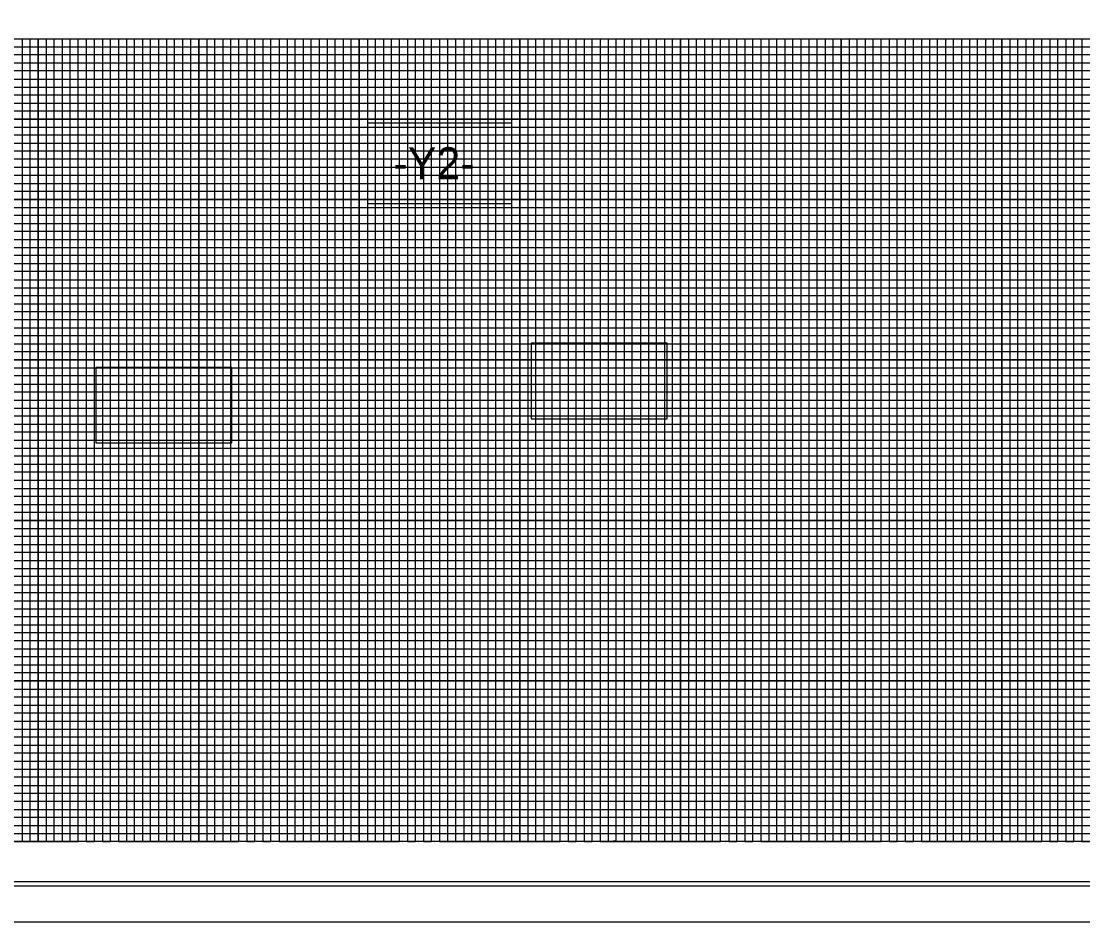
# Model space of a CAD drawing. Extents: x 1650661 to 1652901, y 832691 to 833791.
# Drawn here: x 1651694 to 1652355, y 832691 to 833252 of the extents above; entities that cross this region are included whole.
import ezdxf

# ---------------------------------------------------------------- set-up
doc = ezdxf.new("R2010")
doc.units = 0
for name, color, linetype in [('Exist Vertical Profile Horizontal Axis Label Major', 7, 'Continuous'), ('Prop Grid Mask', 7, 'Continuous'), ('Sheet Cutting Line CELL', 7, 'Continuous'), ('Sheet DOT Grid CELL', 7, 'Continuous'), ('Sheet Layout Profile Border Port 2', 7, 'Continuous'), ('Sheet Plot Border Inside CELL', 7, 'Continuous'), ('Sheet Plot Border Outside CELL', 7, 'Continuous'), ('Sheet Profile CELL', 7, 'Continuous'), ('Sheet Profile Grid Major CELL', 7, 'Continuous'), ('Sheet Profile Grid Middle CELL', 7, 'Continuous'), ('Sheet Profile Grid Minor CELL', 7, 'Continuous')]:
    doc.layers.add(name, color=color, linetype=linetype)

msp = doc.modelspace()

# ---------------------------------------------------------------- linework, layer by layer
at = {"layer": 'Prop Grid Mask'}
for points in [[(1651909.28, 833188.52), (1651909.28, 833138.52), (1651999.28, 833138.52), (1651999.28, 833188.52)], [(1652011.29, 833051.42), (1652011.29, 833004.42), (1652096.04, 833004.42), (1652096.04, 833051.42)], [(1651740.2, 833036.34), (1651740.2, 832989.34), (1651824.95, 832989.34), (1651824.95, 833036.34)]]:
    msp.add_lwpolyline(points, close=True, dxfattribs=at)
at = {"layer": 'Sheet Cutting Line CELL'}
msp.add_line((1651037.28, 832691.02), (1652721.28, 832691.02), dxfattribs=at)
at = {"layer": 'Sheet DOT Grid CELL'}
for p, q in [((1651204.28, 833241.02), (1652704.17, 833241.02)), ((1651704.28, 833241.02), (1651704.28, 832741.02)), ((1651754.28, 833241.02), (1651754.28, 832741.02)), ((1651804.28, 833241.02), (1651804.28, 832741.02)), ((1651854.28, 833241.02), (1651854.28, 832741.02)), ((1651904.28, 833241.02), (1651904.28, 832741.02)), ((1651954.28, 833241.02), (1651954.28, 832741.02)), ((1652004.28, 833241.02), (1652004.28, 832741.02)), ((1652054.28, 833241.02), (1652054.28, 832741.02)), ((1652104.28, 833241.02), (1652104.28, 832741.02)), ((1652154.28, 833241.02), (1652154.28, 832741.02)), ((1652204.28, 833241.02), (1652204.28, 832741.02)), ((1652254.28, 833241.02), (1652254.28, 832741.02)), ((1652304.28, 833241.02), (1652304.28, 832741.02)), ((1652354.28, 833241.02), (1652354.28, 832741.02)), ((1651204.28, 833191.02), (1652704.17, 833191.02)), ((1651204.28, 833141.02), (1652704.17, 833141.02)), ((1651204.28, 833091.02), (1652704.17, 833091.02)), ((1651204.28, 833041.02), (1652704.17, 833041.02)), ((1651204.28, 832991.02), (1652704.17, 832991.02)), ((1651204.28, 832941.02), (1652704.17, 832941.02)), ((1651204.28, 832891.02), (1652704.17, 832891.02)), ((1651204.28, 832841.02), (1652704.17, 832841.02)), ((1651204.28, 832791.02), (1652704.17, 832791.02))]:
    msp.add_line(p, q, dxfattribs=at)
at = {"layer": 'Sheet Layout Profile Border Port 2'}
msp.add_lwpolyline([(1651254.28, 833241.02), (1652654.28, 833241.02), (1652654.28, 832741.02), (1651254.28, 832741.02)], close=True, dxfattribs=at)
at = {"layer": 'Sheet Plot Border Inside CELL'}
msp.add_lwpolyline([(1651050.28, 832713.47), (1652716.78, 832713.47), (1652716.78, 833768.57), (1651050.28, 833768.57)], close=True, dxfattribs=at)
at = {"layer": 'Sheet Plot Border Outside CELL'}
msp.add_lwpolyline([(1651037.28, 832691.02), (1652721.28, 832691.02), (1652721.28, 833791.02), (1651037.28, 833791.02)], close=True, dxfattribs=at)
at = {"layer": 'Sheet Profile CELL'}
for p, q in [((1651204.28, 833241.02), (1652704.28, 833241.02)), ((1652704.28, 832741.02), (1651204.28, 832741.02)), ((1651204.28, 832716.02), (1652704.28, 832716.02))]:
    msp.add_line(p, q, dxfattribs=at)
msp.add_lwpolyline([(1652704.28, 833766.02), (1651204.28, 833766.02), (1651204.28, 832716.02), (1652704.28, 832716.02)], close=True, dxfattribs=at)
at = {"layer": 'Sheet Profile Grid Major CELL'}
for p, q in [((1651704.28, 833241.02), (1651754.28, 833241.02)), ((1651804.28, 833241.02), (1651854.28, 833241.02)), ((1651904.28, 833241.02), (1651954.28, 833241.02)), ((1652004.28, 833241.02), (1652054.28, 833241.02)), ((1652104.28, 833241.02), (1652154.28, 833241.02)), ((1652204.28, 833241.02), (1652254.28, 833241.02)), ((1652304.28, 833241.02), (1652354.28, 833241.02))]:
    msp.add_line(p, q, dxfattribs=at)
for points in [[(1651654.28, 832741.02), (1651704.28, 832741.02), (1651704.28, 833241.02), (1651754.28, 833241.02), (1651754.28, 832741.02), (1651804.28, 832741.02), (1651804.28, 833241.02), (1651854.28, 833241.02), (1651854.28, 832741.02), (1651904.28, 832741.02), (1651904.28, 833241.02), (1651954.28, 833241.02), (1651954.28, 832741.02), (1652004.28, 832741.02), (1652004.28, 833241.02), (1652054.28, 833241.02), (1652054.28, 832741.02), (1652104.28, 832741.02), (1652104.28, 833241.02), (1652154.28, 833241.02), (1652154.28, 832741.02), (1652204.28, 832741.02), (1652204.28, 833241.02), (1652254.28, 833241.02), (1652254.28, 832741.02), (1652304.28, 832741.02), (1652304.28, 833241.02), (1652354.28, 833241.02), (1652354.28, 832741.02), (1652404.28, 832741.02)], [(1652704.28, 833191.02), (1651204.28, 833191.02)], [(1652704.28, 833141.02), (1651204.28, 833141.02), (1651204.28, 833091.02), (1652704.28, 833091.02)], [(1652704.28, 833041.02), (1651204.28, 833041.02), (1651204.28, 832991.02), (1652704.28, 832991.02)], [(1652704.28, 832941.02), (1651204.28, 832941.02), (1651204.28, 832891.02), (1652704.28, 832891.02)], [(1652704.28, 832841.02), (1651204.28, 832841.02), (1651204.28, 832841.02), (1651204.28, 832791.02), (1652704.28, 832791.02)], [(1652704.28, 832741.02), (1651204.28, 832741.02)]]:
    msp.add_lwpolyline(points, dxfattribs=at)
at = {"layer": 'Sheet Profile Grid Middle CELL'}
for points in [[(1651679.28, 832741.02), (1651729.28, 832741.02), (1651729.28, 833241.02), (1651779.28, 833241.02), (1651779.28, 832741.02), (1651829.28, 832741.02), (1651829.28, 832741.02), (1651829.28, 833241.02), (1651879.28, 833241.02), (1651879.28, 832741.02), (1651929.28, 832741.02), (1651929.28, 833241.02), (1651979.28, 833241.02), (1651979.28, 832741.02), (1652029.28, 832741.02), (1652029.28, 833241.02), (1652079.28, 833241.02), (1652079.28, 832741.02), (1652129.28, 832741.02), (1652129.28, 833241.02), (1652179.28, 833241.02), (1652179.28, 832741.02), (1652229.28, 832741.02), (1652229.28, 833241.02), (1652279.28, 833241.02), (1652279.28, 832741.02), (1652329.28, 832741.02), (1652329.28, 833241.02), (1652379.28, 833241.02)], [(1651204.28, 833216.02), (1652704.28, 833216.02)], [(1652704.28, 833166.02), (1651204.28, 833166.02), (1651204.28, 833116.02), (1652704.28, 833116.02)], [(1652704.28, 833066.02), (1651204.28, 833066.02), (1651204.28, 833016.02), (1652704.28, 833016.02)], [(1652704.28, 832966.02), (1651204.28, 832966.02), (1651204.28, 832916.02), (1652704.28, 832916.02)], [(1652704.28, 832866.02), (1651204.28, 832866.02), (1651204.28, 832816.02), (1652704.28, 832816.02)], [(1652704.28, 832766.02), (1651204.28, 832766.02)]]:
    msp.add_lwpolyline(points, dxfattribs=at)
at = {"layer": 'Sheet Profile Grid Minor CELL'}
for p, q in [((1651254.28, 833236.02), (1652654.28, 833236.02)), ((1652654.28, 833231.02), (1651254.28, 833231.02)), ((1651254.28, 833226.02), (1652654.28, 833226.02)), ((1652654.28, 833221.02), (1651254.28, 833221.02)), ((1651254.28, 833211.02), (1652654.28, 833211.02)), ((1652654.28, 833206.02), (1651254.28, 833206.02)), ((1651254.28, 833201.02), (1652654.28, 833201.02)), ((1652654.28, 833196.02), (1651254.28, 833196.02)), ((1651254.28, 833186.02), (1652654.28, 833186.02)), ((1652654.28, 833181.02), (1651254.28, 833181.02)), ((1651254.28, 833176.02), (1652654.28, 833176.02)), ((1652654.28, 833171.02), (1651254.28, 833171.02)), ((1651254.28, 833161.02), (1652654.28, 833161.02)), ((1652654.28, 833156.02), (1651254.28, 833156.02)), ((1651254.28, 833151.02), (1652654.28, 833151.02)), ((1652654.28, 833146.02), (1651254.28, 833146.02)), ((1651254.28, 833136.02), (1652654.28, 833136.02)), ((1652654.28, 833131.02), (1651254.28, 833131.02)), ((1651254.28, 833126.02), (1652654.28, 833126.02)), ((1652654.28, 833121.02), (1651254.28, 833121.02)), ((1651254.28, 833111.02), (1652654.28, 833111.02)), ((1652654.28, 833106.02), (1651254.28, 833106.02)), ((1651254.28, 833101.02), (1652654.28, 833101.02)), ((1652654.28, 833096.02), (1651254.28, 833096.02)), ((1651254.28, 833086.02), (1652654.28, 833086.02)), ((1652654.28, 833081.02), (1651254.28, 833081.02)), ((1651254.28, 833076.02), (1652654.28, 833076.02)), ((1652654.28, 833071.02), (1651254.28, 833071.02)), ((1651254.28, 833061.02), (1652654.28, 833061.02)), ((1652654.28, 833056.02), (1651254.28, 833056.02)), ((1651254.28, 833051.02), (1652654.28, 833051.02)), ((1652654.28, 833046.02), (1651254.28, 833046.17)), ((1651254.28, 833036.02), (1652654.28, 833036.02)), ((1652654.28, 833031.02), (1651254.28, 833031.02)), ((1651254.28, 833026.02), (1652654.28, 833026.02)), ((1652654.28, 833021.02), (1651254.28, 833021.02)), ((1651254.28, 833011.02), (1652654.28, 833011.02)), ((1652654.28, 833006.02), (1651254.28, 833006.02)), ((1651254.28, 833001.02), (1652654.28, 833001.02)), ((1652654.28, 832996.02), (1651254.28, 832996.02)), ((1651254.28, 832986.02), (1652654.28, 832986.02)), ((1652654.28, 832981.02), (1651254.28, 832981.02)), ((1651254.28, 832976.02), (1652654.28, 832976.02)), ((1652654.28, 832971.02), (1651254.28, 832971.02)), ((1651254.28, 832961.02), (1652654.28, 832961.02)), ((1652654.28, 832956.02), (1651254.28, 832956.02)), ((1651254.28, 832951.02), (1652654.28, 832951.02)), ((1652654.28, 832946.02), (1651254.28, 832946.02)), ((1651254.28, 832936.02), (1652654.28, 832936.02)), ((1652654.28, 832931.02), (1651254.28, 832931.02)), ((1651254.28, 832926.02), (1652654.28, 832926.02)), ((1652654.28, 832921.02), (1651254.28, 832921.02)), ((1651254.28, 832911.02), (1652654.28, 832911.02)), ((1652654.28, 832906.02), (1651254.28, 832906.02)), ((1651254.28, 832901.02), (1652654.28, 832901.02)), ((1652654.28, 832896.02), (1651254.28, 832896.02)), ((1651254.28, 832886.02), (1652654.28, 832886.02)), ((1652654.28, 832881.02), (1651254.28, 832881.02)), ((1651254.28, 832876.02), (1652654.28, 832876.02)), ((1652654.28, 832871.02), (1651254.28, 832871.02)), ((1651254.28, 832861.02), (1652654.28, 832861.02)), ((1652654.28, 832856.02), (1651254.28, 832856.02)), ((1651254.28, 832851.02), (1652654.28, 832851.02)), ((1652654.28, 832846.02), (1651254.28, 832846.02)), ((1651254.28, 832836.02), (1652654.28, 832836.02)), ((1652654.28, 832831.02), (1651254.28, 832831.02)), ((1651254.28, 832826.02), (1652654.28, 832826.02)), ((1652654.28, 832821.02), (1651254.28, 832821.02)), ((1651254.28, 832811.02), (1652654.28, 832811.02)), ((1652654.28, 832806.02), (1651254.28, 832806.02)), ((1651254.28, 832801.02), (1652654.28, 832801.02)), ((1652654.28, 832796.02), (1651254.28, 832796.02)), ((1651254.28, 832786.02), (1652654.28, 832786.02)), ((1652654.28, 832781.02), (1651254.28, 832781.02)), ((1651254.28, 832776.02), (1652654.28, 832776.02)), ((1652654.28, 832771.02), (1651254.28, 832771.02)), ((1651254.28, 832761.02), (1652654.28, 832761.02)), ((1652654.28, 832756.02), (1651254.28, 832756.02)), ((1651254.28, 832751.02), (1652654.28, 832751.02)), ((1651254.28, 832746.02), (1652654.28, 832746.02))]:
    msp.add_line(p, q, dxfattribs=at)
for points in [[(1651689.28, 833241.02), (1651694.28, 833241.02), (1651694.28, 832741.02), (1651699.28, 832741.02), (1651699.28, 833241.02), (1651709.28, 833241.02), (1651709.28, 832741.02), (1651714.28, 832741.02), (1651714.28, 833241.02), (1651719.28, 833241.02), (1651719.28, 832741.02), (1651724.28, 832741.02), (1651724.28, 833241.02), (1651734.28, 833241.02), (1651734.28, 832741.02), (1651739.28, 832741.02), (1651739.28, 833241.02), (1651744.28, 833241.02), (1651744.28, 832741.02), (1651749.28, 832741.02), (1651749.28, 833241.02), (1651759.28, 833241.02), (1651759.28, 832741.02), (1651764.28, 832741.02), (1651764.28, 833241.02), (1651769.28, 833241.02), (1651769.28, 832741.02), (1651774.28, 832741.02), (1651774.28, 833241.02), (1651784.28, 833241.02)], [(1651784.28, 833241.02), (1651784.28, 832741.02), (1651789.28, 832741.02), (1651789.28, 833241.02), (1651794.28, 833241.02), (1651794.28, 832741.02), (1651799.28, 832741.02), (1651799.28, 833241.02), (1651809.28, 833241.02), (1651809.28, 832741.02), (1651814.28, 832741.02), (1651814.28, 833241.02), (1651819.28, 833241.02), (1651819.28, 832741.02), (1651824.28, 832741.02), (1651824.28, 833241.02), (1651834.28, 833241.02), (1651834.28, 832741.02), (1651839.28, 832741.02), (1651839.28, 833241.02), (1651844.28, 833241.02), (1651844.28, 832741.02), (1651849.28, 832741.02), (1651849.28, 833241.02), (1651859.28, 833241.02), (1651859.28, 832741.02), (1651864.28, 832741.02), (1651864.28, 833241.02), (1651869.28, 833241.02), (1651869.28, 832741.02), (1651874.28, 832741.02), (1651874.28, 833241.02), (1651884.28, 833241.02), (1651884.28, 832741.02), (1651889.28, 832741.02), (1651889.28, 833241.02), (1651894.28, 833241.02), (1651894.28, 832741.02), (1651899.28, 832741.02), (1651899.28, 833241.02), (1651909.28, 833241.02), (1651909.28, 832741.02), (1651909.28, 832741.02), (1651914.28, 832741.02), (1651914.28, 833241.02), (1651919.28, 833241.02), (1651919.28, 832741.02), (1651924.28, 832741.02), (1651924.28, 833241.02), (1651934.28, 833241.02), (1651934.28, 832741.02), (1651939.28, 832741.02), (1651939.28, 833241.02), (1651944.28, 833241.02), (1651944.28, 832741.02), (1651949.28, 832741.02), (1651949.28, 833241.02), (1651959.28, 833241.02), (1651959.28, 832741.02), (1651964.28, 832741.02), (1651964.28, 833241.02), (1651969.28, 833241.02), (1651969.28, 832741.02), (1651974.28, 832741.02), (1651974.28, 833241.02), (1651984.28, 833241.02), (1651984.28, 832741.02), (1651989.28, 832741.02), (1651989.28, 833241.02), (1651994.28, 833241.02), (1651994.28, 832741.02), (1651999.28, 832741.02), (1651999.28, 833241.02), (1652009.28, 833241.02), (1652009.28, 832741.02), (1652014.28, 832741.02), (1652014.28, 833241.02), (1652019.28, 833241.02), (1652019.28, 832741.02), (1652024.28, 832741.02), (1652024.28, 833241.02), (1652034.28, 833241.02), (1652034.28, 832741.02), (1652039.28, 832741.02), (1652039.28, 833241.02), (1652044.28, 833241.02), (1652044.28, 832741.02), (1652049.28, 832741.02), (1652049.28, 833241.02), (1652059.28, 833241.02), (1652059.28, 832741.02), (1652063.98, 832741.57), (1652064.28, 832741.02), (1652064.28, 833241.02), (1652069.28, 833241.02), (1652069.28, 832741.02), (1652074.28, 832741.02), (1652074.28, 833241.02), (1652084.28, 833241.02), (1652084.28, 832741.02), (1652089.28, 832741.02)], [(1652089.28, 832741.02), (1652089.28, 833241.02), (1652094.28, 833241.02), (1652094.28, 832741.02), (1652099.28, 832741.02), (1652099.28, 833241.02), (1652109.28, 833241.02), (1652109.28, 832741.02), (1652114.28, 832741.02), (1652114.28, 833241.02), (1652119.28, 833241.02), (1652119.28, 832741.02), (1652124.28, 832741.02), (1652124.28, 833241.02), (1652134.28, 833241.02), (1652134.28, 832741.02), (1652139.28, 832741.02), (1652139.28, 833241.02), (1652144.28, 833241.02), (1652144.28, 832741.02), (1652149.28, 832741.02), (1652149.28, 833241.02), (1652159.28, 833241.02), (1652159.28, 832741.02), (1652164.28, 832741.02), (1652164.28, 833241.02), (1652169.28, 833241.02), (1652169.28, 832741.02), (1652174.28, 832741.02), (1652174.28, 833241.02), (1652184.28, 833241.02), (1652184.28, 832741.02), (1652189.28, 832741.02), (1652189.28, 833241.02), (1652194.28, 833241.02), (1652194.28, 832741.02), (1652199.28, 832741.02), (1652199.28, 833241.02), (1652209.28, 833241.02), (1652209.28, 832741.02), (1652214.28, 832741.02), (1652214.28, 833241.02), (1652219.28, 833241.02), (1652219.28, 832741.02), (1652224.28, 832741.02), (1652224.28, 833241.02), (1652234.28, 833241.02), (1652234.28, 832741.02), (1652239.28, 832741.02), (1652239.28, 833241.02), (1652244.28, 833241.02), (1652244.28, 832741.02), (1652249.28, 832741.02), (1652249.28, 833241.02), (1652259.28, 833241.02), (1652259.28, 832741.02), (1652264.28, 832741.02), (1652264.28, 833241.02), (1652269.28, 833241.02), (1652269.28, 832741.02), (1652274.28, 832741.02), (1652274.28, 833241.02), (1652284.28, 833241.02), (1652284.28, 832741.02), (1652289.28, 832741.02), (1652289.28, 833241.02), (1652294.28, 833241.02), (1652294.28, 832741.02), (1652299.28, 832741.02), (1652299.28, 833241.02), (1652309.28, 833241.02), (1652309.28, 832741.02), (1652314.28, 832741.02), (1652314.28, 833241.02), (1652319.28, 833241.02), (1652319.28, 832741.02), (1652324.28, 832741.02), (1652324.28, 833241.02), (1652334.28, 833241.02), (1652334.28, 832741.02), (1652339.28, 832741.02), (1652339.28, 833241.02), (1652344.28, 833241.02), (1652344.28, 832741.02), (1652349.28, 832741.02), (1652349.28, 833241.02), (1652359.28, 833241.02)]]:
    msp.add_lwpolyline(points, dxfattribs=at)

# ---------------------------------------------------------------- texts
at = {"layer": 'Exist Vertical Profile Horizontal Axis Label Major'}
msp.add_text('-Y2-', height=20, dxfattribs=at).set_placement((1651925.52, 833153.52))

doc.saveas('drawing.dxf')
